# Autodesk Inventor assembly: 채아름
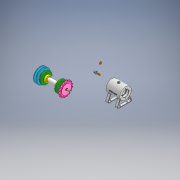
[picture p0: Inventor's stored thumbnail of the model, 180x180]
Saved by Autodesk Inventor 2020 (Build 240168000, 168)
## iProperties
Created: 2021-12
Part Number: 채아름
Document SubType Name: Assembly
Designer: Windows7
Author: Windows7
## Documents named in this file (16)
- C:\Users\Windows7\Desktop\711206V1033\채아름.iam
- C:\Users\Windows7\Desktop\711206V1033\본체.ipt
- C:\Users\Windows7\Desktop\711206V1033\V벨트풀리.ipt
- C:\Users\Windows7\Desktop\711206V1033\너트 M8.ipt
- C:\Users\Windows7\Desktop\711206V1033\니플 M6 x 0.75.ipt
- C:\Users\Windows7\Desktop\711206V1033\베어링 6002.ipt
- C:\Users\Windows7\Desktop\711206V1033\볼트 M4 x 12.ipt
- C:\Users\Windows7\Desktop\711206V1033\볼트 M6 x 8.ipt
- C:\Users\Windows7\Desktop\711206V1033\스프로킷.ipt
- C:\Users\Windows7\Desktop\711206V1033\스프링와셔 8.ipt
- C:\Users\Windows7\Desktop\711206V1033\오일 실 15 x 25 x 7.ipt
- C:\Users\Windows7\Desktop\711206V1033\와셔 6 x 11.5.ipt
- C:\Users\Windows7\Desktop\711206V1033\와셔 8 x 17.ipt
- C:\Users\Windows7\Desktop\711206V1033\축.ipt
- C:\Users\Windows7\Desktop\711206V1033\커버.ipt
- C:\Users\Windows7\Desktop\711206V1033\키 3 x 3.ipt
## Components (4 placed, 3 different names)
1. V벨트풀리:1
2. KS B 2023 6002 - 15 x 32 x 9:1
3. ISO 4762 M4 x 12:1
4. KS B 2023 6002 - 15 x 32 x 9:2
